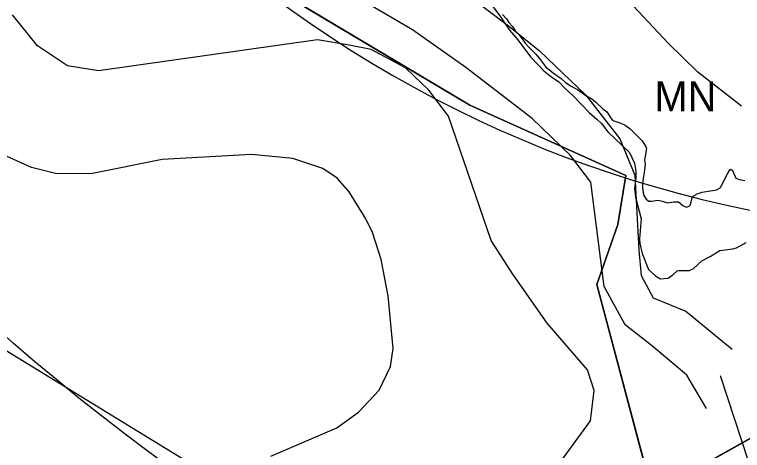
# Model space of a CAD drawing. Extents: x -706130 to -698555, y -971544 to -967260.
# Drawn here: x -704688.5 to -704443.8, y -970419.8 to -970273.1 of the extents above; entities that cross this region are included whole.
import ezdxf

# ---------------------------------------------------------------- set-up
doc = ezdxf.new("R2010")
doc.units = 0
for name, color, linetype in [('BPEJ I-II trida ochrany S', 7, 'Continuous'), ('Docházková izochrona - BUS S', 7, 'Continuous'), ('Docházková izochrona - VLAK N', 7, 'Continuous'), ('KN_Hranice_parcel', 7, 'Continuous'), ('KN_Polygon parcely', 7, 'Continuous'), ('KN_POZEMKY_14_OSTATNI PLOCHA', 7, 'Continuous'), ('KN_POZEMKY_2_ORNA PUDA', 7, 'Continuous'), ('KN_POZEMKY_7_TTP', 7, 'Continuous'), ('KN_VYUZITI_23_ostatni plocha_manipulacni plocha', 7, 'Continuous'), ('Plochy smíšené nezastavěného území všeobecné S', 7, 'Continuous'), ('Plochy zemědělské všeobecné CELEK S', 7, 'Continuous'), ('Regulační bloky v krajině S', 7, 'Continuous'), ('Regulační kódy v krajině S', 7, 'Continuous'), ('Spoje_RR trasy S', 7, 'Continuous'), ('VÝŠKOPIS_vrstevnice doplňková', 7, 'Continuous'), ('VÝŠKOPIS_vrstevnice hlavní', 7, 'Continuous'), ('Záplavové území stanovene S', 7, 'Continuous'), ('Záplavového území_aktivní zóna S', 7, 'Continuous')]:
    doc.layers.add(name, color=color, linetype=linetype)

msp = doc.modelspace()

# ---------------------------------------------------------------- linework, layer by layer
at = {"layer": 'BPEJ I-II trida ochrany S'}
msp.add_line((-704460.72, -970426.66), (-704421.1, -970404.49), dxfattribs=at)
at = {"layer": 'Docházková izochrona - BUS S'}
msp.add_arc((-704361.83, -969946.93), 400, 155.5182, 17.3395, dxfattribs=at)
at = {"layer": 'Docházková izochrona - VLAK N'}
msp.add_circle((-704165.45, -969778.77), 800, dxfattribs=at)
at = {"layer": 'KN_Hranice_parcel'}
for points in [[(-704456.83, -970473.13), (-704474.11, -970434.34), (-704492.75, -970364), (-704485.71, -970343.76), (-704482.97, -970327.34), (-704535.5, -970303.67), (-704598.61, -970265.93), (-704627.27, -970138.62)], [(-704452.01, -970442.24), (-704460.72, -970426.66), (-704421.1, -970404.49)]]:
    msp.add_lwpolyline(points, dxfattribs=at)
at = {"layer": 'KN_Polygon parcely'}
for points in [[(-704474.11, -970434.34), (-704492.75, -970364), (-704485.71, -970343.76), (-704482.97, -970327.34), (-704535.5, -970303.67), (-704598.61, -970265.93), (-704627.27, -970138.62), (-704649.44, -970043.22), (-704652.17, -970031.12), (-704686.38, -969887.56)], [(-704429.39, -970214.99), (-704449.12, -970231.72), (-704487.24, -970219.2), (-704505.81, -970195.93), (-704528.4, -970146.96), (-704544.94, -970123.35), (-704558.36, -970100.79), (-704575.35, -970119.2), (-704604.95, -970130.27), (-704627.27, -970138.62), (-704598.61, -970265.93), (-704535.5, -970303.67), (-704482.97, -970327.34), (-704485.71, -970343.76), (-704492.75, -970364), (-704474.11, -970434.34)], [(-704460.72, -970426.66), (-704421.1, -970404.49)]]:
    msp.add_lwpolyline(points, dxfattribs=at)
msp.add_lwpolyline([(-704452.01, -970442.24), (-704412.74, -970420.26), (-704413.24, -970419.36), (-704421.1, -970404.49), (-704460.72, -970426.66)], close=True, dxfattribs=at)
at = {"layer": 'KN_POZEMKY_14_OSTATNI PLOCHA'}
msp.add_line((-704460.72, -970426.66), (-704421.1, -970404.49), dxfattribs=at)
at = {"layer": 'KN_POZEMKY_2_ORNA PUDA'}
for p, q in [((-704598.61, -970265.93), (-704535.5, -970303.67)), ((-704535.5, -970303.67), (-704482.97, -970327.34)), ((-704482.97, -970327.34), (-704485.71, -970343.76)), ((-704485.71, -970343.76), (-704492.75, -970364)), ((-704492.75, -970364), (-704474.11, -970434.34))]:
    msp.add_line(p, q, dxfattribs=at)
at = {"layer": 'KN_POZEMKY_7_TTP'}
for p, q in [((-704535.5, -970303.67), (-704598.61, -970265.93)), ((-704482.97, -970327.34), (-704535.5, -970303.67)), ((-704485.71, -970343.76), (-704482.97, -970327.34)), ((-704492.75, -970364), (-704485.71, -970343.76)), ((-704474.11, -970434.34), (-704492.75, -970364)), ((-704421.1, -970404.49), (-704460.72, -970426.66))]:
    msp.add_line(p, q, dxfattribs=at)
at = {"layer": 'KN_VYUZITI_23_ostatni plocha_manipulacni plocha'}
msp.add_line((-704460.72, -970426.66), (-704421.1, -970404.49), dxfattribs=at)
at = {"layer": 'Plochy smíšené nezastavěného území všeobecné S'}
for p, q in [((-704598.61, -970265.93), (-704535.5, -970303.67)), ((-704535.5, -970303.67), (-704482.97, -970327.34)), ((-704482.97, -970327.34), (-704485.71, -970343.76)), ((-704485.71, -970343.76), (-704492.75, -970364)), ((-704492.75, -970364), (-704474.11, -970434.34))]:
    msp.add_line(p, q, dxfattribs=at)
at = {"layer": 'Plochy zemědělské všeobecné CELEK S'}
for p, q in [((-704535.5, -970303.67), (-704598.61, -970265.93)), ((-704482.97, -970327.34), (-704535.5, -970303.67)), ((-704485.71, -970343.76), (-704482.97, -970327.34)), ((-704492.75, -970364), (-704485.71, -970343.76)), ((-704474.11, -970434.34), (-704492.75, -970364))]:
    msp.add_line(p, q, dxfattribs=at)
at = {"layer": 'Regulační bloky v krajině S'}
for p, q in [((-704598.61, -970265.93), (-704535.5, -970303.67)), ((-704535.5, -970303.67), (-704598.61, -970265.93)), ((-704535.5, -970303.67), (-704482.97, -970327.34)), ((-704482.97, -970327.34), (-704535.5, -970303.67)), ((-704482.97, -970327.34), (-704485.71, -970343.76)), ((-704485.71, -970343.76), (-704482.97, -970327.34)), ((-704485.71, -970343.76), (-704492.75, -970364)), ((-704492.75, -970364), (-704485.71, -970343.76)), ((-704492.75, -970364), (-704474.11, -970434.34)), ((-704474.11, -970434.34), (-704492.75, -970364))]:
    msp.add_line(p, q, dxfattribs=at)
at = {"layer": 'Spoje_RR trasy S'}
msp.add_lwpolyline([(-703762.9, -970955.81), (-704408.59, -970559.73), (-705036.21, -970174.74)], dxfattribs=at)
at = {"layer": 'VÝŠKOPIS_vrstevnice doplňková'}
for points in [[(-704444.12, -970303.91), (-704458.82, -970292.49), (-704468.8, -970282.79), (-704490.49, -970259.39), (-704512.75, -970234.14), (-704525.44, -970220.87), (-704545.28, -970207.89), (-704560.68, -970199.9), (-704577.38, -970192.34), (-704588.5, -970186.06), (-704596.64, -970180.5), (-704604.34, -970174.22), (-704616.47, -970161.52), (-704624.74, -970148.68), (-704630.74, -970134.7), (-704637.3, -970110.45), (-704646.71, -970070.78), (-704660.7, -970023.13), (-704670.25, -969997.45), (-704673.11, -969988.18)], [(-704571.68, -970245.82), (-704545.71, -970259.3), (-704522.07, -970277.23), (-704512.07, -970285.36), (-704496.52, -970300.28), (-704485.05, -970314.9), (-704479.99, -970327.18), (-704478.69, -970352.45), (-704477.85, -970360.92), (-704473.82, -970368.45), (-704462.86, -970372.98), (-704452.88, -970381.1), (-704447.3, -970385.76)], [(-704455.92, -970405.7), (-704462.51, -970394.51), (-704473.92, -970384.88), (-704483.21, -970377.59), (-704490.3, -970364.6), (-704494.84, -970329.48), (-704501.6, -970320.56), (-704514.49, -970308.11), (-704536.85, -970290.96), (-704554.7, -970278.26), (-704585.97, -970259.91)]]:
    msp.add_lwpolyline(points, dxfattribs=at)
at = {"layer": 'VÝŠKOPIS_vrstevnice hlavní'}
for points in [[(-704512.53, -970433.98), (-704494.87, -970409.8), (-704493.68, -970399.67), (-704495.89, -970392.63), (-704509.44, -970376.94), (-704521.06, -970360.48), (-704528.26, -970349.16), (-704542.68, -970307.32), (-704549.31, -970298.61), (-704557.1, -970291.06), (-704568.67, -970284.94), (-704576.02, -970283.42), (-704586.73, -970281.65), (-704660.33, -970292.11), (-704670.75, -970290.34), (-704680.86, -970283.64), (-704689.22, -970273.19)], [(-704602.34, -970421.75), (-704580.23, -970412.19), (-704572.95, -970406.91), (-704565.96, -970399.5), (-704562.11, -970391.51), (-704561.25, -970385.51), (-704562.97, -970367.82), (-704565.25, -970355.55), (-704568.24, -970346.42), (-704570.39, -970341.86), (-704576.09, -970332.73), (-704580.09, -970328.16), (-704584.94, -970324.88), (-704594.93, -970321.6), (-704608.91, -970320.17), (-704638.87, -970321.88), (-704662.84, -970326.73), (-704674.82, -970326.59), (-704682.81, -970324.59), (-704691.08, -970320.88)], [(-704441.7, -970423.75), (-704451.14, -970394.65)]]:
    msp.add_lwpolyline(points, dxfattribs=at)
at = {"layer": 'Záplavové území stanovene S'}
msp.add_lwpolyline([(-704530.54, -970266.54), (-704525.13, -970273.88), (-704522.18, -970278.33), (-704519.38, -970281.63), (-704515.1, -970287.38), (-704512.62, -970289.88), (-704510.62, -970292.1), (-704508.38, -970293.87), (-704505.52, -970295.77), (-704503.39, -970298.01), (-704500.88, -970300.38), (-704495.32, -970306.07), (-704492.62, -970308.39), (-704491.25, -970309.81), (-704489.12, -970312.56), (-704481.76, -970319.51), (-704480.08, -970323.08), (-704479.61, -970325.88), (-704479.66, -970328.12), (-704480.11, -970331.64), (-704479.8, -970334.55), (-704477.9, -970341.9), (-704478.45, -970348.56), (-704478.34, -970350.12), (-704477.56, -970353.56), (-704475.41, -970358.88), (-704473.09, -970361.09), (-704471.38, -970362.05), (-704468.88, -970361.8), (-704467.31, -970360.84), (-704465.77, -970359.38), (-704465.27, -970359.23), (-704461.62, -970359.23), (-704460.27, -970358.62), (-704457.47, -970356.03), (-704454.7, -970354.55), (-704451.38, -970352.48), (-704447.02, -970351.98), (-704445.82, -970351.68), (-704442.53, -970349.78)], dxfattribs=at)
at = {"layer": 'Záplavového území_aktivní zóna S'}
msp.add_lwpolyline([(-704524.44, -970273.12), (-704523.12, -970274.62), (-704522.38, -970275.75), (-704521.12, -970277.12), (-704520.19, -970278.62), (-704519.06, -970279.75), (-704517.5, -970281.75), (-704516.88, -970282.75), (-704515.62, -970284.12), (-704513.38, -970286.38), (-704512.12, -970287.75), (-704509.69, -970291.06), (-704508.75, -970291.62), (-704507.38, -970292.88), (-704504.75, -970294.62), (-704503.38, -970295.88), (-704501.62, -970297.12), (-704499.25, -970298.38), (-704496.12, -970300.62), (-704494.5, -970301.5), (-704493.25, -970302.5), (-704490.75, -970304.88), (-704489.44, -970305.81), (-704487.69, -970308.44), (-704487, -970308.88), (-704484.75, -970309.62), (-704483.25, -970310.38), (-704481.62, -970311.62), (-704477.56, -970315.62), (-704476.38, -970317.38), (-704476.06, -970318.25), (-704476.56, -970320.75), (-704476.69, -970322.12), (-704476.56, -970323.38), (-704476.69, -970325.5), (-704477.12, -970327.5), (-704477.44, -970330.06), (-704477.44, -970331.44), (-704477.12, -970333.75), (-704476.19, -970335.25), (-704475.25, -970335.88), (-704474.38, -970335.88), (-704472.12, -970335.56), (-704470.75, -970335.88), (-704469.06, -970336.44), (-704466.88, -970336.12), (-704465.31, -970336.19), (-704463.88, -970337.38), (-704462.75, -970337.94), (-704461.75, -970337.62), (-704461.31, -970337.12), (-704460.88, -970335.12), (-704460.56, -970334.31), (-704459, -970333.5), (-704457.38, -970332.88), (-704452.56, -970332.06), (-704451.31, -970331.44), (-704450.81, -970330.69), (-704448.88, -970326.75), (-704448.06, -970325.38), (-704447.69, -970325.12), (-704447.12, -970325.56), (-704446.06, -970328.19), (-704444.88, -970328.62), (-704443, -970328.94)], dxfattribs=at)

# ---------------------------------------------------------------- texts
at = {"layer": 'Regulační kódy v krajině S'}
msp.add_text('MN', height=10, dxfattribs=at).set_placement((-704473.37, -970305.65))

doc.saveas('drawing.dxf')
